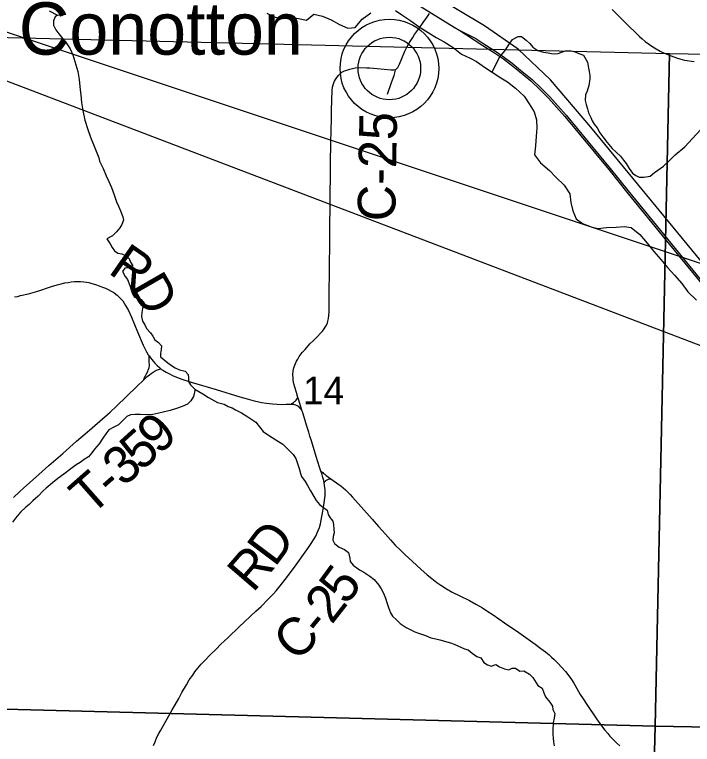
# Model space of a CAD drawing. Extents: x -7.1 to 34, y 0 to 22.
# Drawn here: x 6.724 to 7.746, y 15.673 to 16.774 of the extents above; entities that cross this region are included whole.
import ezdxf

# ---------------------------------------------------------------- set-up
doc = ezdxf.new("R2010")
doc.units = 0
for name, color, linetype in [('GM_X_County_Road', 7, 'Continuous'), ('GM_X_County_Road_Text', 7, 'Continuous'), ('GM_X_Major_River', 7, 'Continuous'), ('GM_X_Minor_River', 7, 'Continuous'), ('GM_X_Rail_Line', 7, 'Continuous'), ('GM_X_Section', 7, 'Continuous'), ('GM_X_Section_Text', 7, 'Continuous'), ('GM_X_State_Route', 7, 'Continuous'), ('GM_X_Township_Road', 7, 'Continuous'), ('GM_X_Township_Road_Text', 7, 'Continuous'), ('GM_X_Unincorporated', 7, 'Continuous'), ('GM_X_Unincorporated_Location', 7, 'Continuous'), ('GM_X_Unincorporated_Text', 7, 'Continuous'), ('SH_Text', 7, 'Continuous')]:
    doc.layers.add(name, color=color, linetype=linetype)

msp = doc.modelspace()

# ---------------------------------------------------------------- linework, layer by layer
at = {"layer": 'GM_X_County_Road'}
for points in [[(7.1571, 16.1773), (7.1555, 16.1824), (7.152, 16.194), (7.1512, 16.1965), (7.1489, 16.2039), (7.1466, 16.2121), (7.1451, 16.2171), (7.1444, 16.2197), (7.1438, 16.2231), (7.1437, 16.2254), (7.1434, 16.2312), (7.1439, 16.2363), (7.1445, 16.2395), (7.1455, 16.2428), (7.1475, 16.2476), (7.149, 16.2511), (7.1509, 16.2545), (7.1532, 16.2582), (7.1576, 16.2641), (7.1618, 16.2687), (7.1692, 16.2773), (7.1744, 16.2824), (7.1806, 16.2885), (7.1853, 16.2935), (7.1883, 16.2967), (7.1907, 16.3), (7.1924, 16.3024), (7.1941, 16.3054), (7.1956, 16.309), (7.1963, 16.3115), (7.1973, 16.3156), (7.1978, 16.3203), (7.198, 16.326), (7.1981, 16.3328), (7.1983, 16.3627), (7.1985, 16.3787), (7.1986, 16.3851), (7.1988, 16.3953), (7.1989, 16.406), (7.199, 16.4171), (7.1991, 16.4407), (7.1992, 16.4487), (7.1993, 16.4607), (7.1995, 16.4794), (7.1996, 16.4919), (7.1999, 16.5122), (7.2001, 16.5218), (7.2003, 16.5407), (7.2004, 16.5522), (7.2008, 16.5786), (7.2014, 16.6022), (7.2017, 16.6145), (7.2019, 16.6304), (7.2022, 16.6448), (7.2027, 16.6606), (7.2032, 16.665), (7.2041, 16.6682), (7.2051, 16.6713), (7.2063, 16.6741), (7.2077, 16.6765), (7.2098, 16.6796), (7.2128, 16.6832), (7.2148, 16.6852), (7.2173, 16.6873), (7.2202, 16.689), (7.223, 16.6903), (7.2262, 16.6913), (7.2292, 16.6921), (7.2334, 16.6931), (7.2377, 16.6939), (7.2427, 16.6944), (7.2552, 16.6942), (7.2597, 16.694), (7.2707, 16.6932), (7.2916, 16.6909), (7.2957, 16.6911), (7.2981, 16.6917), (7.2991, 16.6923), (7.3003, 16.6932), (7.3017, 16.6947), (7.3031, 16.6968), (7.3045, 16.6995), (7.308, 16.7082), (7.3126, 16.7192), (7.3156, 16.7254), (7.3179, 16.7296), (7.3213, 16.7352), (7.3243, 16.7398), (7.3272, 16.7442), (7.3345, 16.7546), (7.3402, 16.7627), (7.3458, 16.7703), (7.3498, 16.7761)], [(6.7232, 16.3483), (6.728, 16.3491), (6.7327, 16.3502), (6.7444, 16.3531), (6.7585, 16.3571), (6.779, 16.3638), (6.7876, 16.3664), (6.7938, 16.368), (6.7992, 16.3694), (6.8046, 16.3702), (6.8091, 16.3708), (6.8138, 16.3713), (6.8183, 16.3715), (6.8228, 16.3713), (6.8281, 16.3709), (6.8319, 16.3704), (6.8356, 16.3698), (6.8403, 16.3686), (6.8457, 16.367), (6.851, 16.3651), (6.8562, 16.3632), (6.8607, 16.3613), (6.8647, 16.3593), (6.8691, 16.3571), (6.8731, 16.3548), (6.8761, 16.3525), (6.8781, 16.3508), (6.8814, 16.348), (6.8842, 16.3451), (6.8867, 16.3421), (6.889, 16.3387), (6.891, 16.3354), (6.8953, 16.3276), (6.8998, 16.3177), (6.9091, 16.2954), (6.9176, 16.2753), (6.9204, 16.2693), (6.9226, 16.2652), (6.9251, 16.261), (6.9266, 16.2591), (6.9284, 16.2565), (6.9325, 16.2512), (6.935, 16.2484), (6.9386, 16.2446), (6.942, 16.2415), (6.9442, 16.2398), (6.9454, 16.2389), (6.9471, 16.2378), (6.9522, 16.2347), (6.9571, 16.2319), (6.9628, 16.2293), (6.9693, 16.2265), (6.9761, 16.2241), (6.99, 16.2196), (7.0278, 16.2085), (7.0632, 16.1976), (7.0747, 16.1942), (7.0849, 16.1914), (7.09, 16.1903), (7.0961, 16.1891), (7.1036, 16.1879), (7.1128, 16.1868), (7.1199, 16.1862), (7.1271, 16.186), (7.1332, 16.1861), (7.1379, 16.1862), (7.1404, 16.1863)], [(7.1404, 16.1863), (7.1428, 16.1879), (7.1445, 16.1891), (7.146, 16.1903), (7.1474, 16.1915), (7.1482, 16.1924), (7.1494, 16.194), (7.1506, 16.1956), (7.1512, 16.1965)], [(7.1404, 16.1863), (7.1441, 16.1861), (7.1455, 16.1859), (7.1476, 16.1853), (7.1493, 16.1844), (7.1513, 16.1832), (7.1531, 16.1814), (7.1551, 16.1794), (7.1571, 16.1773)], [(7.1858, 16.0853), (7.1854, 16.0866), (7.1838, 16.0912), (7.1786, 16.1072), (7.1714, 16.1309), (7.1691, 16.1381), (7.1673, 16.1442), (7.1642, 16.1546), (7.1619, 16.1619), (7.1584, 16.1733), (7.1571, 16.1773)], [(6.9334, 15.6708), (6.9355, 15.6767), (6.9384, 15.6835), (6.9414, 15.6893), (6.944, 15.694), (6.9614, 15.7247), (6.9659, 15.7326), (6.9712, 15.7418), (6.9761, 15.7511), (6.9827, 15.7626), (6.9872, 15.7701), (6.9923, 15.7772), (6.9953, 15.782), (7.0001, 15.7878), (7.0051, 15.7936), (7.0112, 15.8001), (7.0187, 15.8077), (7.0276, 15.8166), (7.0348, 15.8238), (7.0457, 15.8343), (7.0626, 15.85), (7.0876, 15.8737), (7.0957, 15.8811), (7.1063, 15.892), (7.114, 15.9001), (7.1182, 15.9047), (7.1284, 15.917), (7.1319, 15.9215), (7.1445, 15.9384), (7.151, 15.9473), (7.1597, 15.9593), (7.167, 15.9698), (7.1722, 15.9774), (7.1762, 15.9838), (7.1779, 15.9869), (7.1803, 15.992), (7.1817, 15.9954), (7.1835, 16.0003), (7.185, 16.0056), (7.1863, 16.0113), (7.1888, 16.0248), (7.1902, 16.0337), (7.1921, 16.0482), (7.1922, 16.051), (7.192, 16.057), (7.1914, 16.0635), (7.1909, 16.0676), (7.1902, 16.071), (7.1889, 16.0758), (7.1871, 16.0817), (7.1858, 16.0853)], [(7.1858, 16.0853), (7.1874, 16.084), (7.1886, 16.083), (7.1899, 16.0819), (7.1916, 16.0805), (7.1939, 16.0786), (7.197, 16.076), (7.2006, 16.0736), (7.2129, 16.065), (7.2157, 16.0629), (7.2194, 16.06), (7.2228, 16.0572), (7.2259, 16.0541), (7.2297, 16.0502), (7.2334, 16.0461), (7.2465, 16.0313), (7.2632, 16.0126), (7.2729, 16.0015), (7.2831, 15.9899), (7.2907, 15.9815), (7.298, 15.9737), (7.3066, 15.9652), (7.3124, 15.9596), (7.3242, 15.9487), (7.3368, 15.9372), (7.3463, 15.9287), (7.353, 15.9231), (7.3607, 15.9172), (7.3665, 15.9132), (7.3754, 15.9075), (7.384, 15.9027), (7.3956, 15.8969), (7.4101, 15.8897), (7.4198, 15.8845), (7.4294, 15.8787), (7.4361, 15.8744), (7.4458, 15.8681), (7.4626, 15.8564), (7.4843, 15.8414), (7.5091, 15.8239), (7.5177, 15.8177), (7.5248, 15.8123), (7.5301, 15.8077), (7.5339, 15.8043), (7.5378, 15.8008), (7.5436, 15.795), (7.5489, 15.7894), (7.5547, 15.7826), (7.5598, 15.7762), (7.5637, 15.7705), (7.5673, 15.7652), (7.5722, 15.7571), (7.577, 15.7482), (7.5814, 15.7414), (7.5871, 15.7329), (7.6018, 15.7111), (7.6092, 15.7008), (7.6143, 15.6941), (7.6185, 15.6889), (7.6219, 15.685), (7.6277, 15.6793), (7.6325, 15.6744), (7.637, 15.6706)], [(7.1909, 16.0676), (7.1919, 16.0692), (7.1926, 16.0702), (7.1934, 16.071), (7.1943, 16.0716), (7.1952, 16.0721), (7.1962, 16.0726), (7.1973, 16.0729), (7.2006, 16.0736)]]:
    msp.add_lwpolyline(points, dxfattribs=at)
at = {"layer": 'GM_X_Major_River'}
for points in [[(6.7759, 16.7801), (6.7881, 16.7738), (6.8007, 16.7751)], [(7.2984, 16.7804), (7.308, 16.7741), (7.3214, 16.7651), (7.334, 16.7562), (7.3474, 16.7476), (7.3597, 16.7398), (7.3719, 16.7331), (7.3853, 16.725), (7.398, 16.7149), (7.411, 16.7086), (7.4205, 16.7034), (7.4339, 16.6941), (7.4442, 16.6877), (7.4573, 16.6792), (7.4672, 16.6732), (7.4795, 16.6635), (7.4925, 16.6512), (7.4999, 16.6399), (7.5076, 16.6278), (7.5112, 16.6157), (7.5117, 16.6028), (7.5104, 16.5911), (7.5094, 16.5763), (7.5081, 16.5626), (7.5173, 16.5506), (7.5308, 16.539), (7.5404, 16.5288), (7.5527, 16.5169), (7.5616, 16.5037), (7.5629, 16.4908), (7.5657, 16.4783), (7.5708, 16.4659), (7.5807, 16.4592), (7.5937, 16.454), (7.6036, 16.4515), (7.6169, 16.4532), (7.6313, 16.4537), (7.6438, 16.4543), (7.6541, 16.4532)], [(7.1044, 16.7765), (7.1167, 16.7706), (7.1292, 16.7685), (7.1425, 16.7702), (7.152, 16.7688), (7.1638, 16.7662), (7.1751, 16.7751), (7.188, 16.7722), (7.201, 16.7663), (7.2136, 16.7597), (7.2262, 16.7541), (7.2376, 16.755), (7.2481, 16.7677), (7.2613, 16.7769)], [(7.6541, 16.4532), (7.6671, 16.4424), (7.6783, 16.4296), (7.6879, 16.4169), (7.6987, 16.4045), (7.7088, 16.3928), (7.7191, 16.3812), (7.7303, 16.3685), (7.7396, 16.3561), (7.7523, 16.3433)]]:
    msp.add_lwpolyline(points, dxfattribs=at)
at = {"layer": 'GM_X_Minor_River'}
for points in [[(6.7881, 16.7738), (6.785, 16.7713), (6.7824, 16.7648), (6.7825, 16.7587), (6.786, 16.7516), (6.7903, 16.7455), (6.7945, 16.7403), (6.8022, 16.7301), (6.8073, 16.7226), (6.8112, 16.7135), (6.8191, 16.6885), (6.8208, 16.6767), (6.8221, 16.6661), (6.8225, 16.6611), (6.8234, 16.6531), (6.8243, 16.6417), (6.8264, 16.6296), (6.8296, 16.6152), (6.834, 16.6008), (6.8383, 16.5894), (6.8438, 16.5758), (6.8509, 16.5584), (6.8517, 16.553), (6.8572, 16.5421), (6.8619, 16.5311), (6.8658, 16.5224), (6.8697, 16.5133), (6.8737, 16.5024), (6.8772, 16.4918), (6.8804, 16.4853), (6.8835, 16.4782), (6.8867, 16.4691), (6.8879, 16.4641), (6.8853, 16.4576), (6.8823, 16.4526), (6.8771, 16.4465), (6.8712, 16.4407), (6.8625, 16.436), (6.8676, 16.4284), (6.8707, 16.4228), (6.8745, 16.4179), (6.8795, 16.4141), (6.8852, 16.4135), (6.8901, 16.4113), (6.8963, 16.4064), (6.8986, 16.4007), (6.9021, 16.3954), (6.8969, 16.3923), (6.89, 16.3915), (6.8863, 16.3864), (6.8906, 16.3793), (6.8941, 16.3744), (6.8972, 16.3657), (6.8996, 16.3589), (6.9016, 16.3528), (6.9043, 16.3479), (6.9093, 16.3461), (6.9146, 16.3442), (6.9192, 16.3386), (6.9167, 16.3309), (6.9156, 16.3248), (6.915, 16.3187), (6.9166, 16.3115), (6.9201, 16.3059), (6.9228, 16.3006), (6.9286, 16.2938), (6.9324, 16.2889), (6.9352, 16.2836), (6.9405, 16.2792), (6.9451, 16.2743), (6.9448, 16.2689), (6.9438, 16.2628), (6.9439, 16.2579), (6.9546, 16.2489), (6.9603, 16.2448), (6.9657, 16.2411), (6.9725, 16.2382), (6.9809, 16.236), (6.9855, 16.2311), (6.986, 16.2262), (6.986, 16.2205), (6.9891, 16.2156), (6.9957, 16.2092), (7.0075, 16.2021), (7.0163, 16.1962), (7.0297, 16.1888), (7.0399, 16.1863), (7.0457, 16.1829), (7.0517, 16.1807), (7.0571, 16.1778), (7.0659, 16.173), (7.0754, 16.167), (7.0876, 16.1592), (7.0985, 16.1453), (7.1065, 16.1397), (7.118, 16.1323), (7.1283, 16.1259), (7.1356, 16.1188), (7.144, 16.1102), (7.1479, 16.1042), (7.1507, 16.0966)], [(7.4442, 16.6877), (7.4541, 16.7084), (7.459, 16.7142), (7.4631, 16.7196), (7.4675, 16.7257), (7.4708, 16.7315), (7.4749, 16.7369), (7.4836, 16.7416), (7.4885, 16.7413), (7.4954, 16.7361), (7.5008, 16.7308), (7.5058, 16.7252), (7.513, 16.7203), (7.5218, 16.7178), (7.5286, 16.7168), (7.5335, 16.7157), (7.5389, 16.7154), (7.5438, 16.7159), (7.5502, 16.7182), (7.5551, 16.7198), (7.5604, 16.7203), (7.568, 16.7189), (7.5752, 16.7156), (7.582, 16.713), (7.5879, 16.7028), (7.5895, 16.6937), (7.5904, 16.6884), (7.5916, 16.6827), (7.5917, 16.6774), (7.5899, 16.6674), (7.5874, 16.6587), (7.5848, 16.6533), (7.5845, 16.6449), (7.5858, 16.6385), (7.5881, 16.632), (7.5897, 16.626), (7.5929, 16.6191), (7.5952, 16.6139), (7.5979, 16.6089), (7.6026, 16.6037), (7.6068, 16.5961), (7.6111, 16.5901), (7.6176, 16.5815), (7.6254, 16.5724), (7.638, 16.5608), (7.6423, 16.5548), (7.6465, 16.5499), (7.6508, 16.542), (7.6562, 16.5352), (7.6612, 16.5315), (7.6661, 16.5289), (7.6729, 16.529), (7.6824, 16.5307), (7.6891, 16.5361), (7.694, 16.5396), (7.7026, 16.5458), (7.7116, 16.554), (7.7205, 16.5629), (7.7347, 16.5749), (7.7463, 16.5876), (7.759, 16.6011)], [(6.9958, 16.2091), (6.9936, 16.1977), (6.9895, 16.1912), (6.9847, 16.1862), (6.9764, 16.1826), (6.9692, 16.1802), (6.9583, 16.177), (6.9458, 16.1738), (6.9319, 16.1709), (6.9224, 16.1704), (6.9129, 16.1706), (6.9054, 16.1705), (6.8986, 16.17), (6.8929, 16.1677), (6.8862, 16.1611), (6.8802, 16.1549), (6.8735, 16.1514), (6.8659, 16.1478), (6.8611, 16.1417), (6.8567, 16.1348), (6.8511, 16.1263), (6.844, 16.1186), (6.8403, 16.1128), (6.8351, 16.1066), (6.8287, 16.1027), (6.8227, 16.0985), (6.8167, 16.0946), (6.8085, 16.0887), (6.798, 16.0806), (6.789, 16.074), (6.7808, 16.0674), (6.7714, 16.0596), (6.7666, 16.0553), (6.7591, 16.0472), (6.7513, 16.0403), (6.7453, 16.0348), (6.7404, 16.031), (6.7326, 16.0232), (6.7248, 16.014), (6.7203, 16.0082)], [(7.1507, 16.0966), (7.153, 16.089), (7.155, 16.0818), (7.1566, 16.0769), (7.162, 16.0697), (7.1655, 16.0637), (7.1702, 16.0554), (7.1752, 16.0467), (7.1787, 16.0411), (7.1837, 16.0351), (7.1895, 16.0302), (7.1952, 16.0261), (7.1968, 16.02), (7.1999, 16.0147), (7.2038, 16.0095), (7.2046, 16.0045), (7.2055, 15.9977), (7.2059, 15.992), (7.2045, 15.9867), (7.2038, 15.9809), (7.2062, 15.976), (7.2134, 15.9704), (7.2214, 15.9671), (7.2272, 15.9623), (7.2292, 15.9539), (7.2297, 15.9486), (7.2343, 15.9433), (7.2442, 15.9363), (7.2503, 15.9329), (7.2595, 15.9266), (7.266, 15.9214), (7.2733, 15.9131), (7.2768, 15.9074), (7.2803, 15.901), (7.2831, 15.8935), (7.2855, 15.887), (7.2878, 15.8794), (7.291, 15.8715), (7.2937, 15.8662), (7.3002, 15.8602), (7.3052, 15.855), (7.3144, 15.8494), (7.3274, 15.8427), (7.3331, 15.8405), (7.3434, 15.8373), (7.3514, 15.8336), (7.359, 15.8322), (7.365, 15.8304), (7.3814, 15.8261), (7.3871, 15.8239), (7.3924, 15.8213), (7.4027, 15.8169), (7.408, 15.8154), (7.4142, 15.8102), (7.4211, 15.8054), (7.4272, 15.8032), (7.4314, 15.7964), (7.4371, 15.7927), (7.4425, 15.7908), (7.4496, 15.7932), (7.4554, 15.7899), (7.463, 15.787), (7.4691, 15.7855), (7.4743, 15.7879), (7.4796, 15.7876), (7.4861, 15.7835), (7.4922, 15.784), (7.5006, 15.7788), (7.5056, 15.7735), (7.5133, 15.7615), (7.5198, 15.7574), (7.5222, 15.7506), (7.5249, 15.7445), (7.5311, 15.7366), (7.535, 15.7306), (7.5358, 15.7253), (7.5386, 15.7192), (7.5379, 15.7124), (7.5361, 15.7055), (7.5355, 15.6944), (7.5356, 15.688), (7.5361, 15.6823), (7.5369, 15.6766), (7.5377, 15.6705)]]:
    msp.add_lwpolyline(points, dxfattribs=at)
at = {"layer": 'GM_X_Rail_Line'}
for points in [[(7.1815, 16.8829), (7.387, 16.7554), (7.3952, 16.7504), (7.4194, 16.7384), (7.4318, 16.7303), (7.4492, 16.7191), (7.4628, 16.7099), (7.4745, 16.7009), (7.4872, 16.6908), (7.5045, 16.6766), (7.5186, 16.6627), (7.5314, 16.6502), (7.5434, 16.6367), (7.5559, 16.6226), (7.6223, 16.5423), (7.6496, 16.5083), (7.7095, 16.4348), (7.7692, 16.3616)], [(7.7949, 16.3595), (7.593, 16.6046), (7.5322, 16.6759), (7.4836, 16.7221), (7.4325, 16.7577), (7.35, 16.8072)], [(7.3952, 16.7504), (7.4057, 16.744), (7.4303, 16.7279), (7.4476, 16.7167), (7.4611, 16.7076), (7.4728, 16.6987), (7.4854, 16.6886), (7.5026, 16.6745), (7.5166, 16.6607), (7.5294, 16.6482), (7.5413, 16.6348), (7.5537, 16.6208), (7.6201, 16.5405), (7.6474, 16.5066), (7.7073, 16.433), (7.767, 16.3599)]]:
    msp.add_lwpolyline(points, dxfattribs=at)
at = {"layer": 'GM_X_Section'}
for points in [[(7.7117, 16.7156), (7.6901, 15.7003), (6.6705, 15.7268), (6.6929, 16.7402)], [(7.7117, 16.7156), (8.7236, 16.6977), (8.7045, 15.6816), (7.6901, 15.7003)], [(7.6901, 15.7003), (7.6641, 14.6933), (6.6482, 14.7054), (6.6705, 15.7268)], [(7.6901, 15.7003), (8.7045, 15.6816), (8.6861, 14.6719), (7.6641, 14.6933)]]:
    msp.add_lwpolyline(points, close=True, dxfattribs=at)
at = {"layer": 'GM_X_State_Route'}
msp.add_lwpolyline([(7.6255, 16.7822), (7.6521, 16.7553), (7.6589, 16.7487), (7.6663, 16.7416), (7.6703, 16.7381), (7.6753, 16.7339), (7.6814, 16.7293), (7.6864, 16.7259), (7.6917, 16.7226), (7.6979, 16.7191), (7.7018, 16.7172), (7.708, 16.7145), (7.7143, 16.712), (7.7226, 16.7091), (7.7275, 16.7076), (7.7342, 16.7059), (7.7386, 16.705), (7.7448, 16.704), (7.749, 16.7038)], dxfattribs=at)
at = {"layer": 'GM_X_Township_Road'}
for points in [[(7.2939, 16.6762), (7.2962, 16.6825), (7.2968, 16.6846), (7.2977, 16.6885), (7.2981, 16.6917)], [(7.2861, 16.6544), (7.2923, 16.6718), (7.2939, 16.6762)], [(6.9185, 16.2231), (6.9193, 16.2254), (6.9211, 16.2289), (6.9228, 16.2323), (6.9244, 16.2355), (6.9253, 16.2377), (6.9263, 16.24), (6.9267, 16.2419), (6.927, 16.2448), (6.9267, 16.2506), (6.9265, 16.2541), (6.9266, 16.2591)], [(6.722, 16.0456), (6.7309, 16.054), (6.7375, 16.0601), (6.7549, 16.0757), (6.7754, 16.0937), (6.7961, 16.1118), (6.8172, 16.1303), (6.8329, 16.1442), (6.8522, 16.1605), (6.8677, 16.1743), (6.8773, 16.1834), (6.9082, 16.2129), (6.9185, 16.2231), (6.9212, 16.2258), (6.9236, 16.2279), (6.9272, 16.2308), (6.9297, 16.2327), (6.9325, 16.2347), (6.9357, 16.2366), (6.9379, 16.2377), (6.9409, 16.2388), (6.9442, 16.2398)]]:
    msp.add_lwpolyline(points, dxfattribs=at)
at = {"layer": 'GM_X_Unincorporated'}
for radius in [0.0744, 0.0472]:
    msp.add_circle((7.2891, 16.6931), radius, dxfattribs=at)
at = {"layer": 'GM_X_Unincorporated_Location'}
msp.add_line((7.2891, 16.6931), (7.2891, 16.6931), dxfattribs=at)
at = {"layer": 'SH_Text'}
msp.add_lwpolyline([(5.1735, 17.2614), (9.3262, 15.8766), (9.3261, 15.6767)], close=True, dxfattribs=at)

# ---------------------------------------------------------------- texts
at = {"layer": 'GM_X_County_Road_Text'}
for s, height, rotation, p in [('C-25', 0.05682, 88.9662, (7.2978, 16.4621)), ('R', 0.0568, 325.0953, (6.8631, 16.3851)), ('D', 0.0568, 299.931, (6.8969, 16.3632)), ('D', 0.0568, 53.1804, (7.1162, 15.939)), ('R', 0.0568, 49.3233, (7.0832, 15.9004)), ('5', 0.0568, 53.6791, (7.2247, 15.8815)), ('2', 0.0568, 51.9858, (7.2021, 15.8525)), ('C', 0.0568, 44.448, (7.1485, 15.7956)), ('-', 0.0568, 50.7452, (7.1865, 15.8333))]:
    msp.add_text(s, height=height, rotation=rotation, dxfattribs=at).set_placement(p)
at = {"layer": 'GM_X_Section_Text'}
msp.add_text('14', height=0.04186, rotation=0, dxfattribs=at).set_placement((7.1587, 16.186))
at = {"layer": 'GM_X_Township_Road_Text'}
for s, rotation, p in [('9', 43.5523, (6.9417, 16.1085)), ('5', 42.0841, (6.9146, 16.0839)), ('3', 41.6112, (6.888, 16.0603)), ('T', 41.3641, (6.8384, 16.0166)), ('-', 41.4024, (6.8704, 16.0448))]:
    msp.add_text(s, height=0.0568, rotation=rotation, dxfattribs=at).set_placement(p)
at = {"layer": 'GM_X_Unincorporated_Text'}
msp.add_text('Conotton', height=0.07898, rotation=0, dxfattribs=at).set_placement((6.7299, 16.714))

doc.saveas('drawing.dxf')
